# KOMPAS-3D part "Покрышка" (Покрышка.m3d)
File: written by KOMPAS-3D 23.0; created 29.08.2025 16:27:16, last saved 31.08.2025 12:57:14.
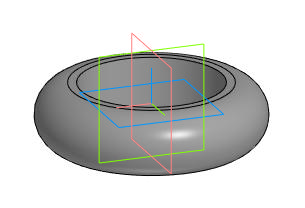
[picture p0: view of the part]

Document properties: Автор: Lost; Полное имя файла: C:\Users\Lost\Desktop\Вариант 1\Покрышка.m3d

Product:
- Part/product: Покрышка
    Масса: 0.975545

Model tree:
1. Эскиз:1  (with: Элемент вращения:2)  (labels: C:\Users\Lost\Desktop\Вариант 1\Сборка колеса.a3d)
2. Элемент вращения:2
     Угол 1 = 360

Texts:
  Смещение (% от длины кривой)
